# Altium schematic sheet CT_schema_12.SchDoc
size 742 x 377 mm
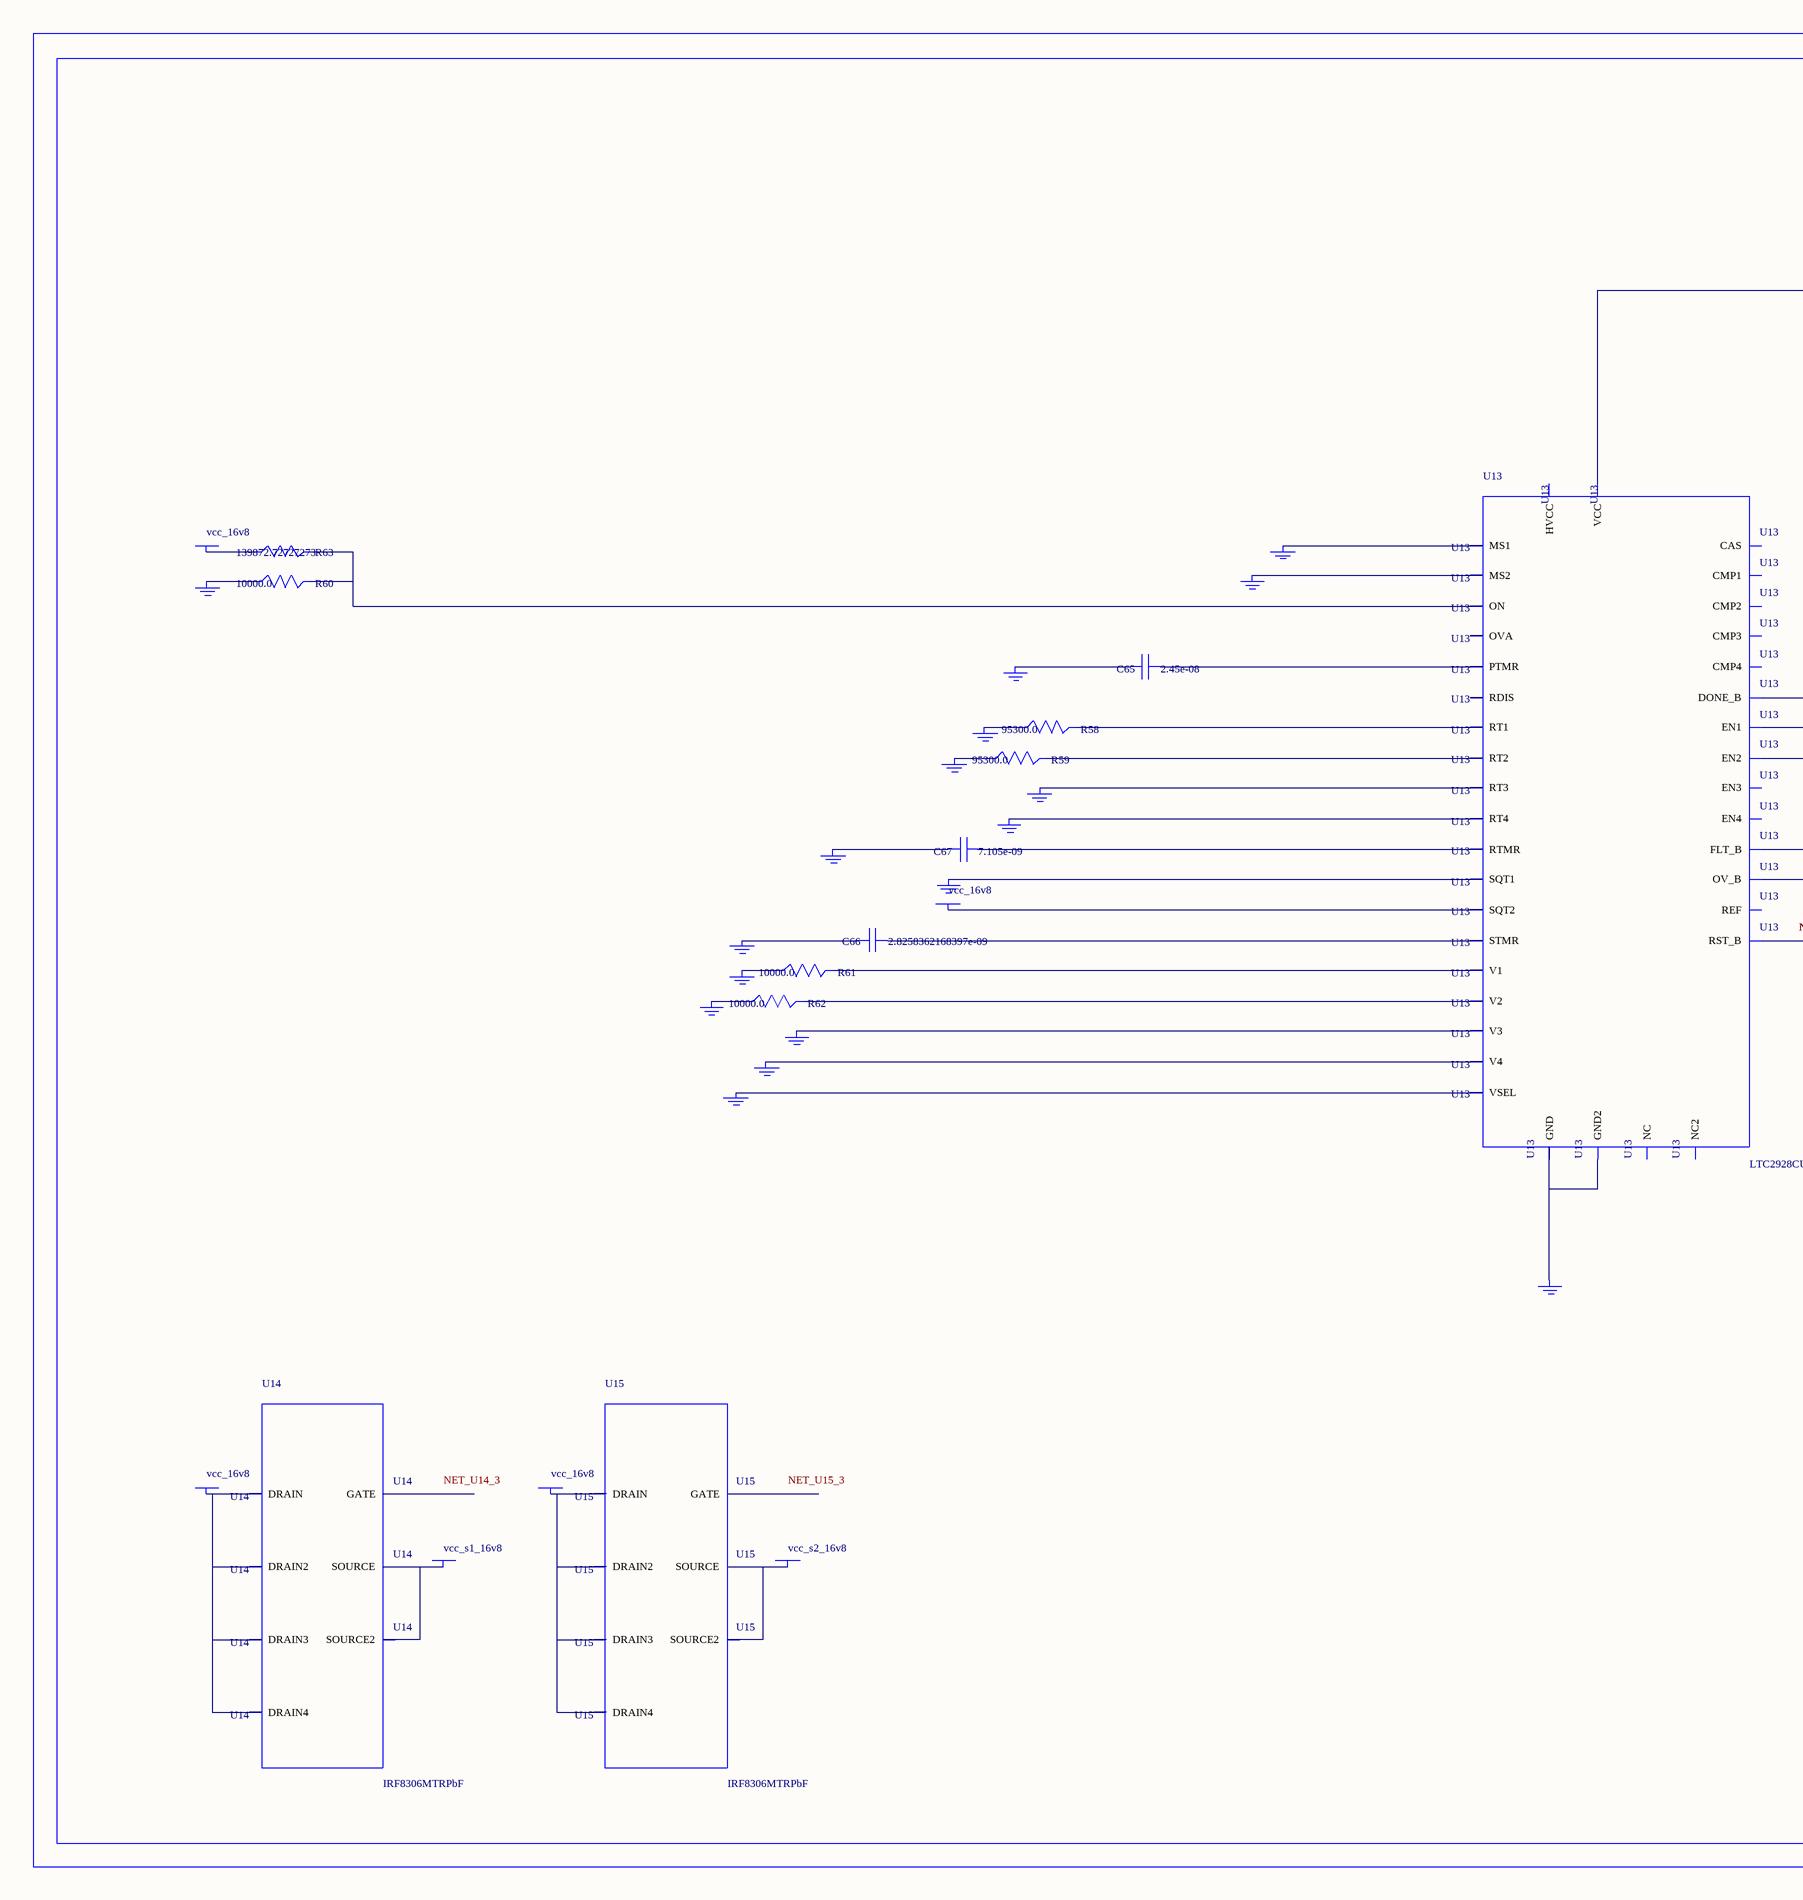
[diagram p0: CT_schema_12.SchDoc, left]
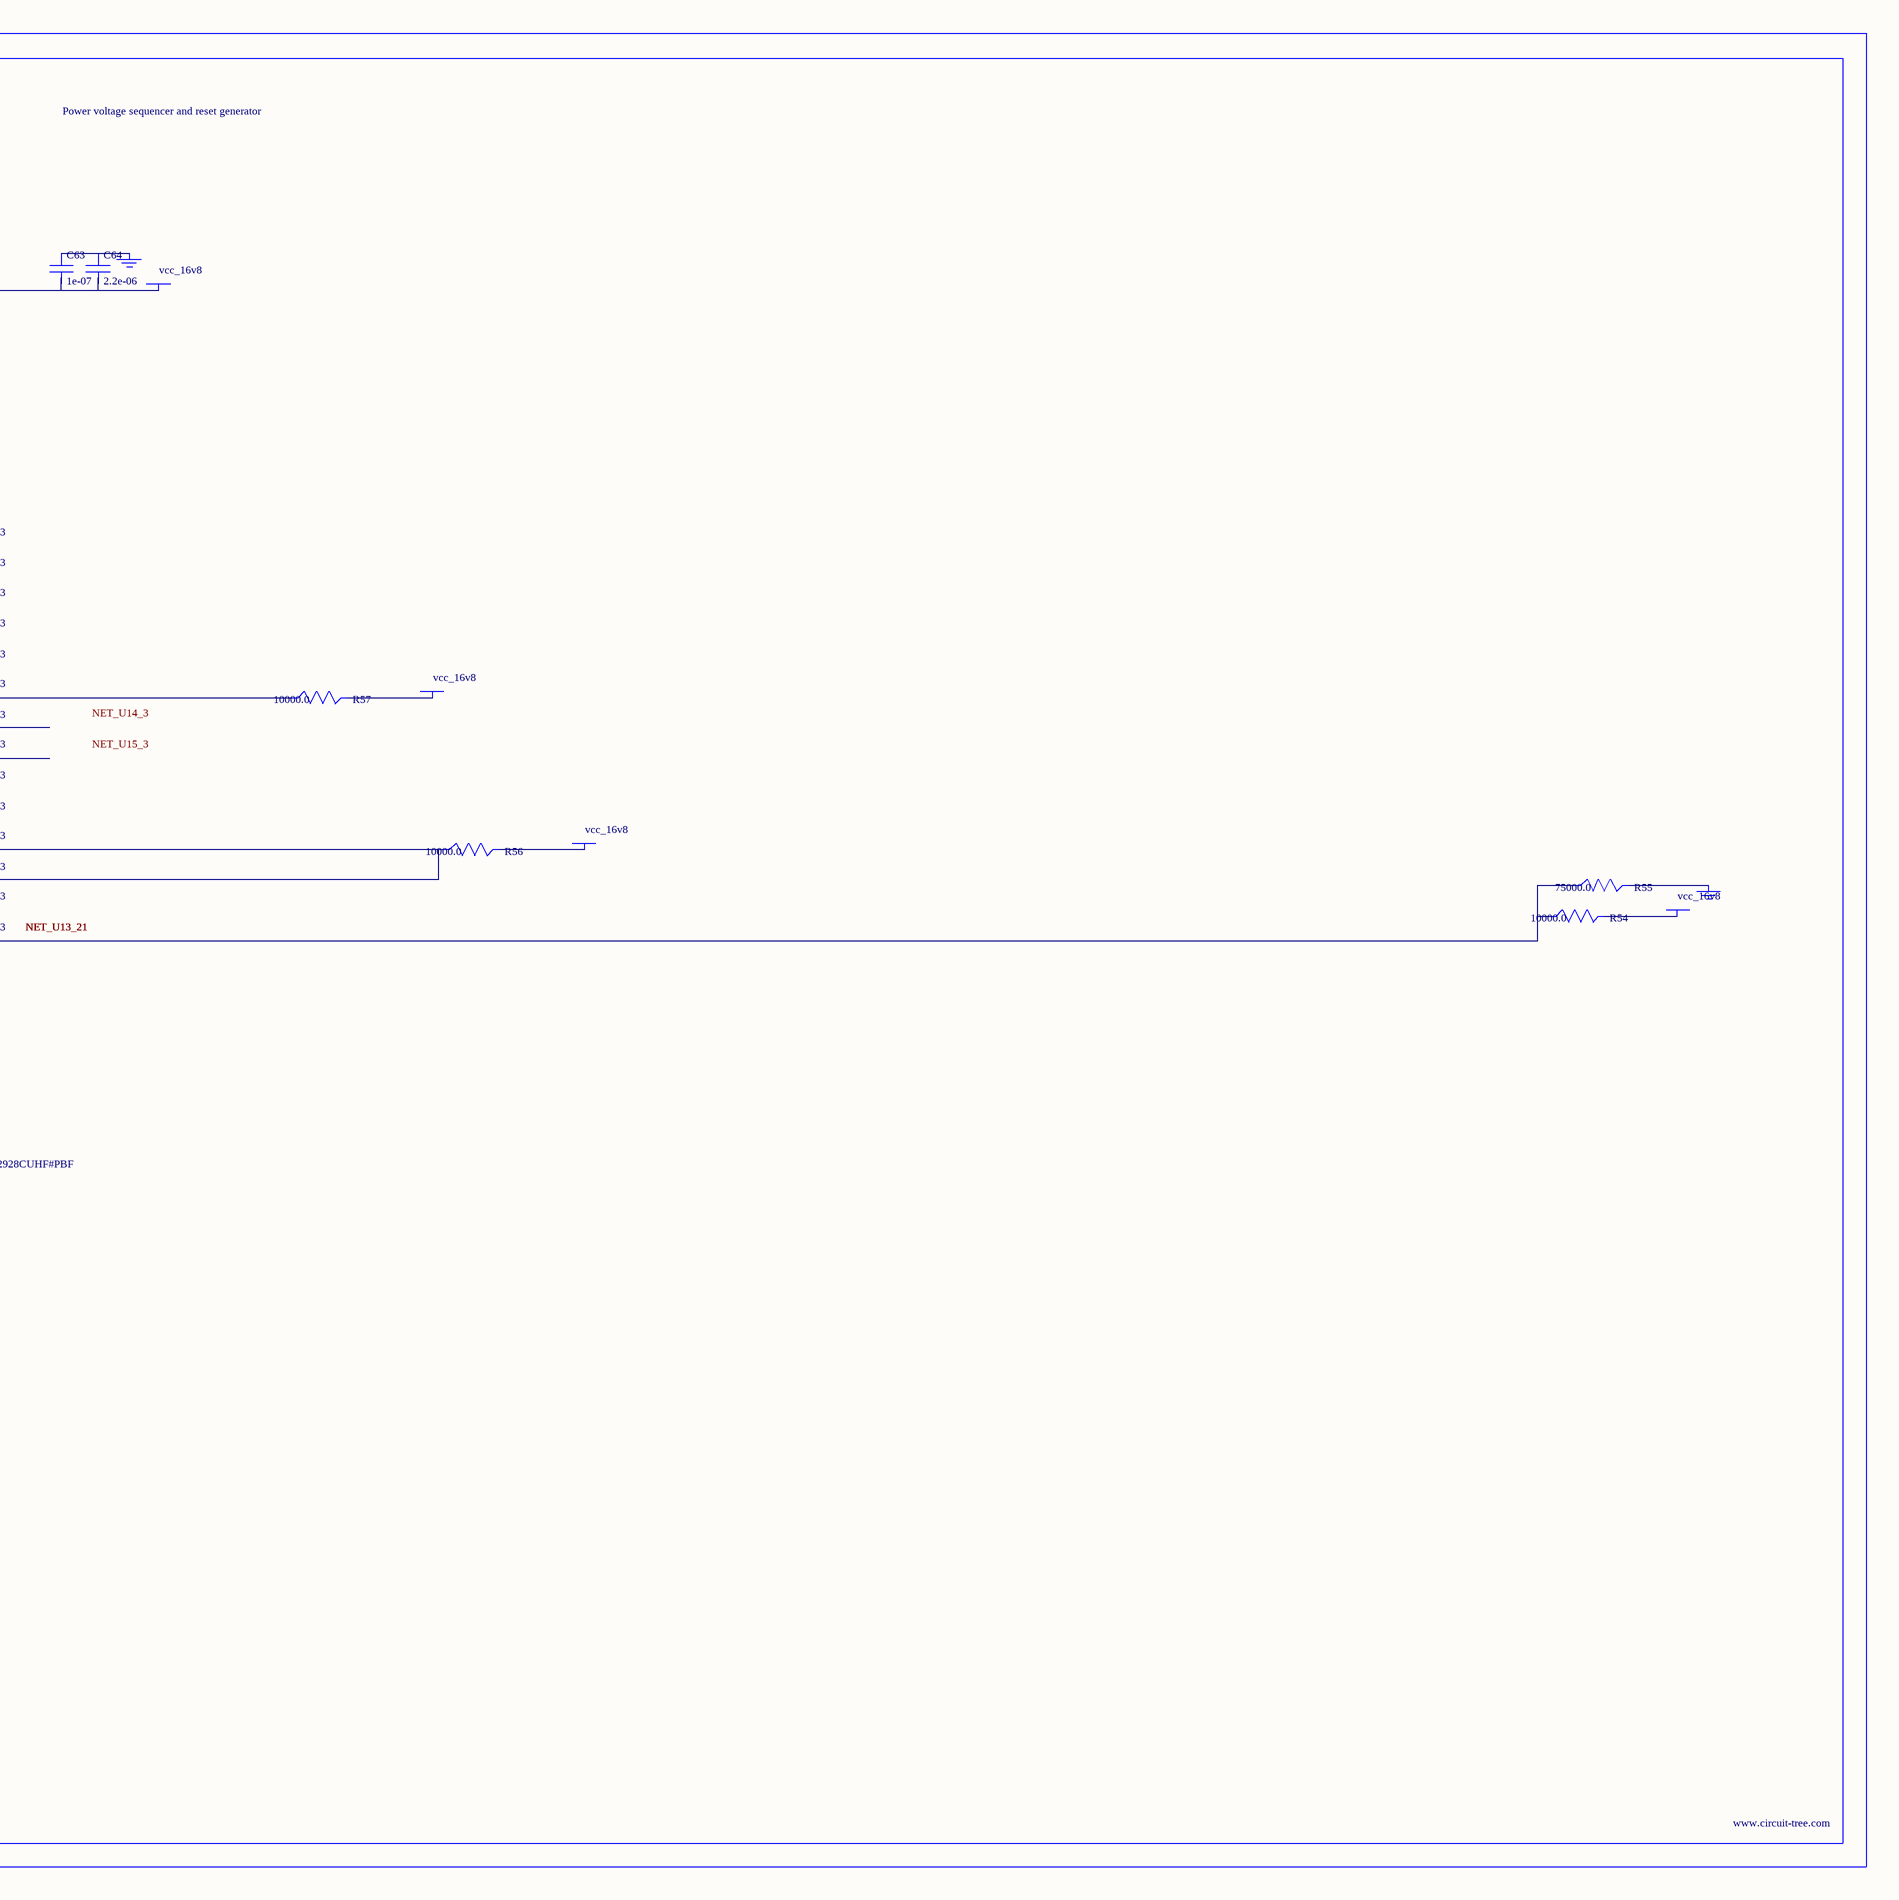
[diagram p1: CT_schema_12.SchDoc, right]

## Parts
BORDER11  (no value)
C63  1e-07  [C0402]
C64  2.2e-06  [C0603]
C65  2.45e-08  [R0603]
C66  2.8258362168397e-09  [R0603]
C67  7.105e-09  [R0603]
GND_INSTANCE_11_0  (no value)
GND_INSTANCE_11_1  (no value)
GND_INSTANCE_11_2  (no value)
GND_INSTANCE_11_3  (no value)
GND_INSTANCE_11_4  (no value)
GND_INSTANCE_11_5  (no value)
GND_INSTANCE_11_6  (no value)
GND_INSTANCE_11_7  (no value)
GND_INSTANCE_11_8  (no value)
GND_INSTANCE_11_9  (no value)
GND_INSTANCE_11_10  (no value)
GND_INSTANCE_11_11  (no value)
GND_INSTANCE_11_12  (no value)
GND_INSTANCE_11_13  (no value)
GND_INSTANCE_11_14  (no value)
GND_INSTANCE_11_15  (no value)
GND_INSTANCE_11_16  (no value)
GND_INSTANCE_11_17  (no value)
GND_INSTANCE_11_18  (no value)
POWER_INSTANCE_11_0  vcc_16v8
POWER_INSTANCE_11_1  vcc_16v8
POWER_INSTANCE_11_2  vcc_16v8
POWER_INSTANCE_11_3  vcc_16v8
POWER_INSTANCE_11_4  vcc_16v8
POWER_INSTANCE_11_5  vcc_16v8
POWER_INSTANCE_11_6  vcc_16v8
POWER_INSTANCE_11_7  vcc_s1_16v8
POWER_INSTANCE_11_8  vcc_16v8
POWER_INSTANCE_11_9  vcc_s2_16v8
R54  10000.0  [R0603]
R55  75000.0  [R0603]
R56  10000.0  [R0603]
R57  10000.0  [R0603]
R58  95300.0  [R0603]
R59  95300.0  [R0603]
R60  10000.0  [R0603]
R61  10000.0  [R0603]
R62  10000.0  [R0603]
R63  139872.72727273  [R0603]
U13  LTC2928CUHF#PBF  [QFN-38_UHF]
U14  IRF8306MTRPbF  [IRF8306MTRPBF]
U15  IRF8306MTRPbF  [IRF8306MTRPBF]

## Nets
NetC63_1: C63.1 C64.1 GND_INSTANCE_11_10.0(GND)
NetC63_2: C63.2 C64.2 POWER_INSTANCE_11_5.0(PWR) U13.22(VCC)
NetC65_1: C65.1 U13.27(PTMR)
NetC65_2: C65.2 GND_INSTANCE_11_13.0(GND)
NetC66_1: C66.1 U13.26(STMR)
NetC66_2: C66.2 GND_INSTANCE_11_12.0(GND)
NetC67_1: C67.1 U13.28(RTMR)
NetC67_2: C67.2 GND_INSTANCE_11_14.0(GND)
NetGND_INSTANCE_11_0_0: GND_INSTANCE_11_0.0(GND) R61.1
NetGND_INSTANCE_11_1_0: GND_INSTANCE_11_1.0(GND) R58.1
NetGND_INSTANCE_11_2_0: GND_INSTANCE_11_2.0(GND) R59.1
NetGND_INSTANCE_11_3_0: GND_INSTANCE_11_3.0(GND) U13.8(RT3)
NetGND_INSTANCE_11_4_0: GND_INSTANCE_11_4.0(GND) U13.9(RT4)
NetGND_INSTANCE_11_5_0: GND_INSTANCE_11_5.0(GND) U13.10(SQT1)
NetGND_INSTANCE_11_6_0: GND_INSTANCE_11_6.0(GND) U13.12(MS1)
NetGND_INSTANCE_11_7_0: GND_INSTANCE_11_7.0(GND) U13.13(MS2)
NetGND_INSTANCE_11_8_0: GND_INSTANCE_11_8.0(GND) R60.1
NetGND_INSTANCE_11_9_0: GND_INSTANCE_11_9.0(GND) R55.2
NetGND_INSTANCE_11_11_0: GND_INSTANCE_11_11.0(GND) U13.25(VSEL)
NetGND_INSTANCE_11_15_0: GND_INSTANCE_11_15.0(GND) U13.30(V4)
NetGND_INSTANCE_11_16_0: GND_INSTANCE_11_16.0(GND) U13.32(V3)
NetGND_INSTANCE_11_17_0: GND_INSTANCE_11_17.0(GND) R62.1
NetGND_INSTANCE_11_18_0: GND_INSTANCE_11_18.0(GND) U13.24(GND) U13.39(GND2)
NetPOWER_INSTANCE_11_0_0: POWER_INSTANCE_11_0.0(PWR) U13.11(SQT2)
NetPOWER_INSTANCE_11_1_0: POWER_INSTANCE_11_1.0(PWR) R63.1
NetPOWER_INSTANCE_11_2_0: POWER_INSTANCE_11_2.0(PWR) R57.2
NetPOWER_INSTANCE_11_3_0: POWER_INSTANCE_11_3.0(PWR) R56.2
NetPOWER_INSTANCE_11_4_0: POWER_INSTANCE_11_4.0(PWR) R54.2
NetPOWER_INSTANCE_11_6_0: POWER_INSTANCE_11_6.0(PWR) U14.1(DRAIN) U14.2(DRAIN2) U14.6(DRAIN3) U14.7(DRAIN4)
NetPOWER_INSTANCE_11_7_0: POWER_INSTANCE_11_7.0(PWR) U14.4(SOURCE) U14.5(SOURCE2)
NetPOWER_INSTANCE_11_8_0: POWER_INSTANCE_11_8.0(PWR) U15.1(DRAIN) U15.2(DRAIN2) U15.6(DRAIN3) U15.7(DRAIN4)
NetPOWER_INSTANCE_11_9_0: POWER_INSTANCE_11_9.0(PWR) U15.4(SOURCE) U15.5(SOURCE2)
NetR54_1: R54.1 R55.1 U13.21(RST_B)
NetR56_1: R56.1 U13.19(FLT_B) U13.20(OV_B)
NetR57_1: R57.1 U13.18(DONE_B)
NetR58_2: R58.2 U13.6(RT1)
NetR59_2: R59.2 U13.7(RT2)
NetR60_2: R60.2 R63.2 U13.16(ON)
NetR61_2: R61.2 U13.3(V1)
NetR62_2: R62.2 U13.38(V2)

Not connected (* = marked no-connect by the designer): U13 1(OVA) 2(EN1) 4(NC) 5(REF) 14(RDIS) 15(CAS) 17(NC2) 23(HVCC) 29(EN4) 31(EN3) 33(CMP3) 34(CMP4) 35(CMP1) 36(CMP2) 37(EN2); U14 3(GATE); U15 3(GATE)

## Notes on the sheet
- Labels drawn without touching a wire or pin: NET_U14_3, NET_U15_3

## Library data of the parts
BORDER11 = BORDER_PAGE11
C63 = C0402C104K3RACTU
C64 = GRM188R61H225KE1115D
C65 = C65
C66 = C66
C67 = C67
GND_INSTANCE_11_0-GND_INSTANCE_11_18 = GND
POWER_INSTANCE_11_0-POWER_INSTANCE_11_9 = PWR
R54 R56 R57 R60-R62 = RC0603JR-0710KL
R55 = RC0603JR-0775KL
R58 R59 = RC0603FR-0795K3L
R63 = R63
